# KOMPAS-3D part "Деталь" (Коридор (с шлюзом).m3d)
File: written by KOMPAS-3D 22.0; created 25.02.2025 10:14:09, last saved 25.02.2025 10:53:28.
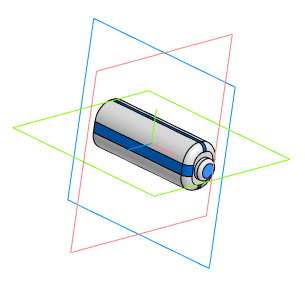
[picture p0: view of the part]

Document properties: Автор: Пользователь Windows; Полное имя файла: C:\Users\Student\Documents\Картошечка\База Сабнатика\Коридор\Коридор (с шлюзом).m3d

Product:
- Part/product: Деталь
    Масса: 0.031677

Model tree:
1. Эскиз:1
2. Элемент выдавливания:1
     Расстояние 1 = 30
3. Элемент выдавливания:3  (with: Элемент выдавливания:1)
     Расстояние 1 = 3
4. Скругление:1  (with: Элемент выдавливания:3)
     Радиус = 2
5. Эскиз:3  (with: Элемент выдавливания:3)
6. Элемент выдавливания:4
     Расстояние 1 = 2
7. Скругление:2  (with: Элемент выдавливания:4)
     Радиус = 1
